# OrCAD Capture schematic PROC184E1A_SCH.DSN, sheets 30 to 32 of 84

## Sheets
30 34. GESI EXPANSION_CONN: size C; title: GESI_EXP_CONN; note: PROC184_SCH
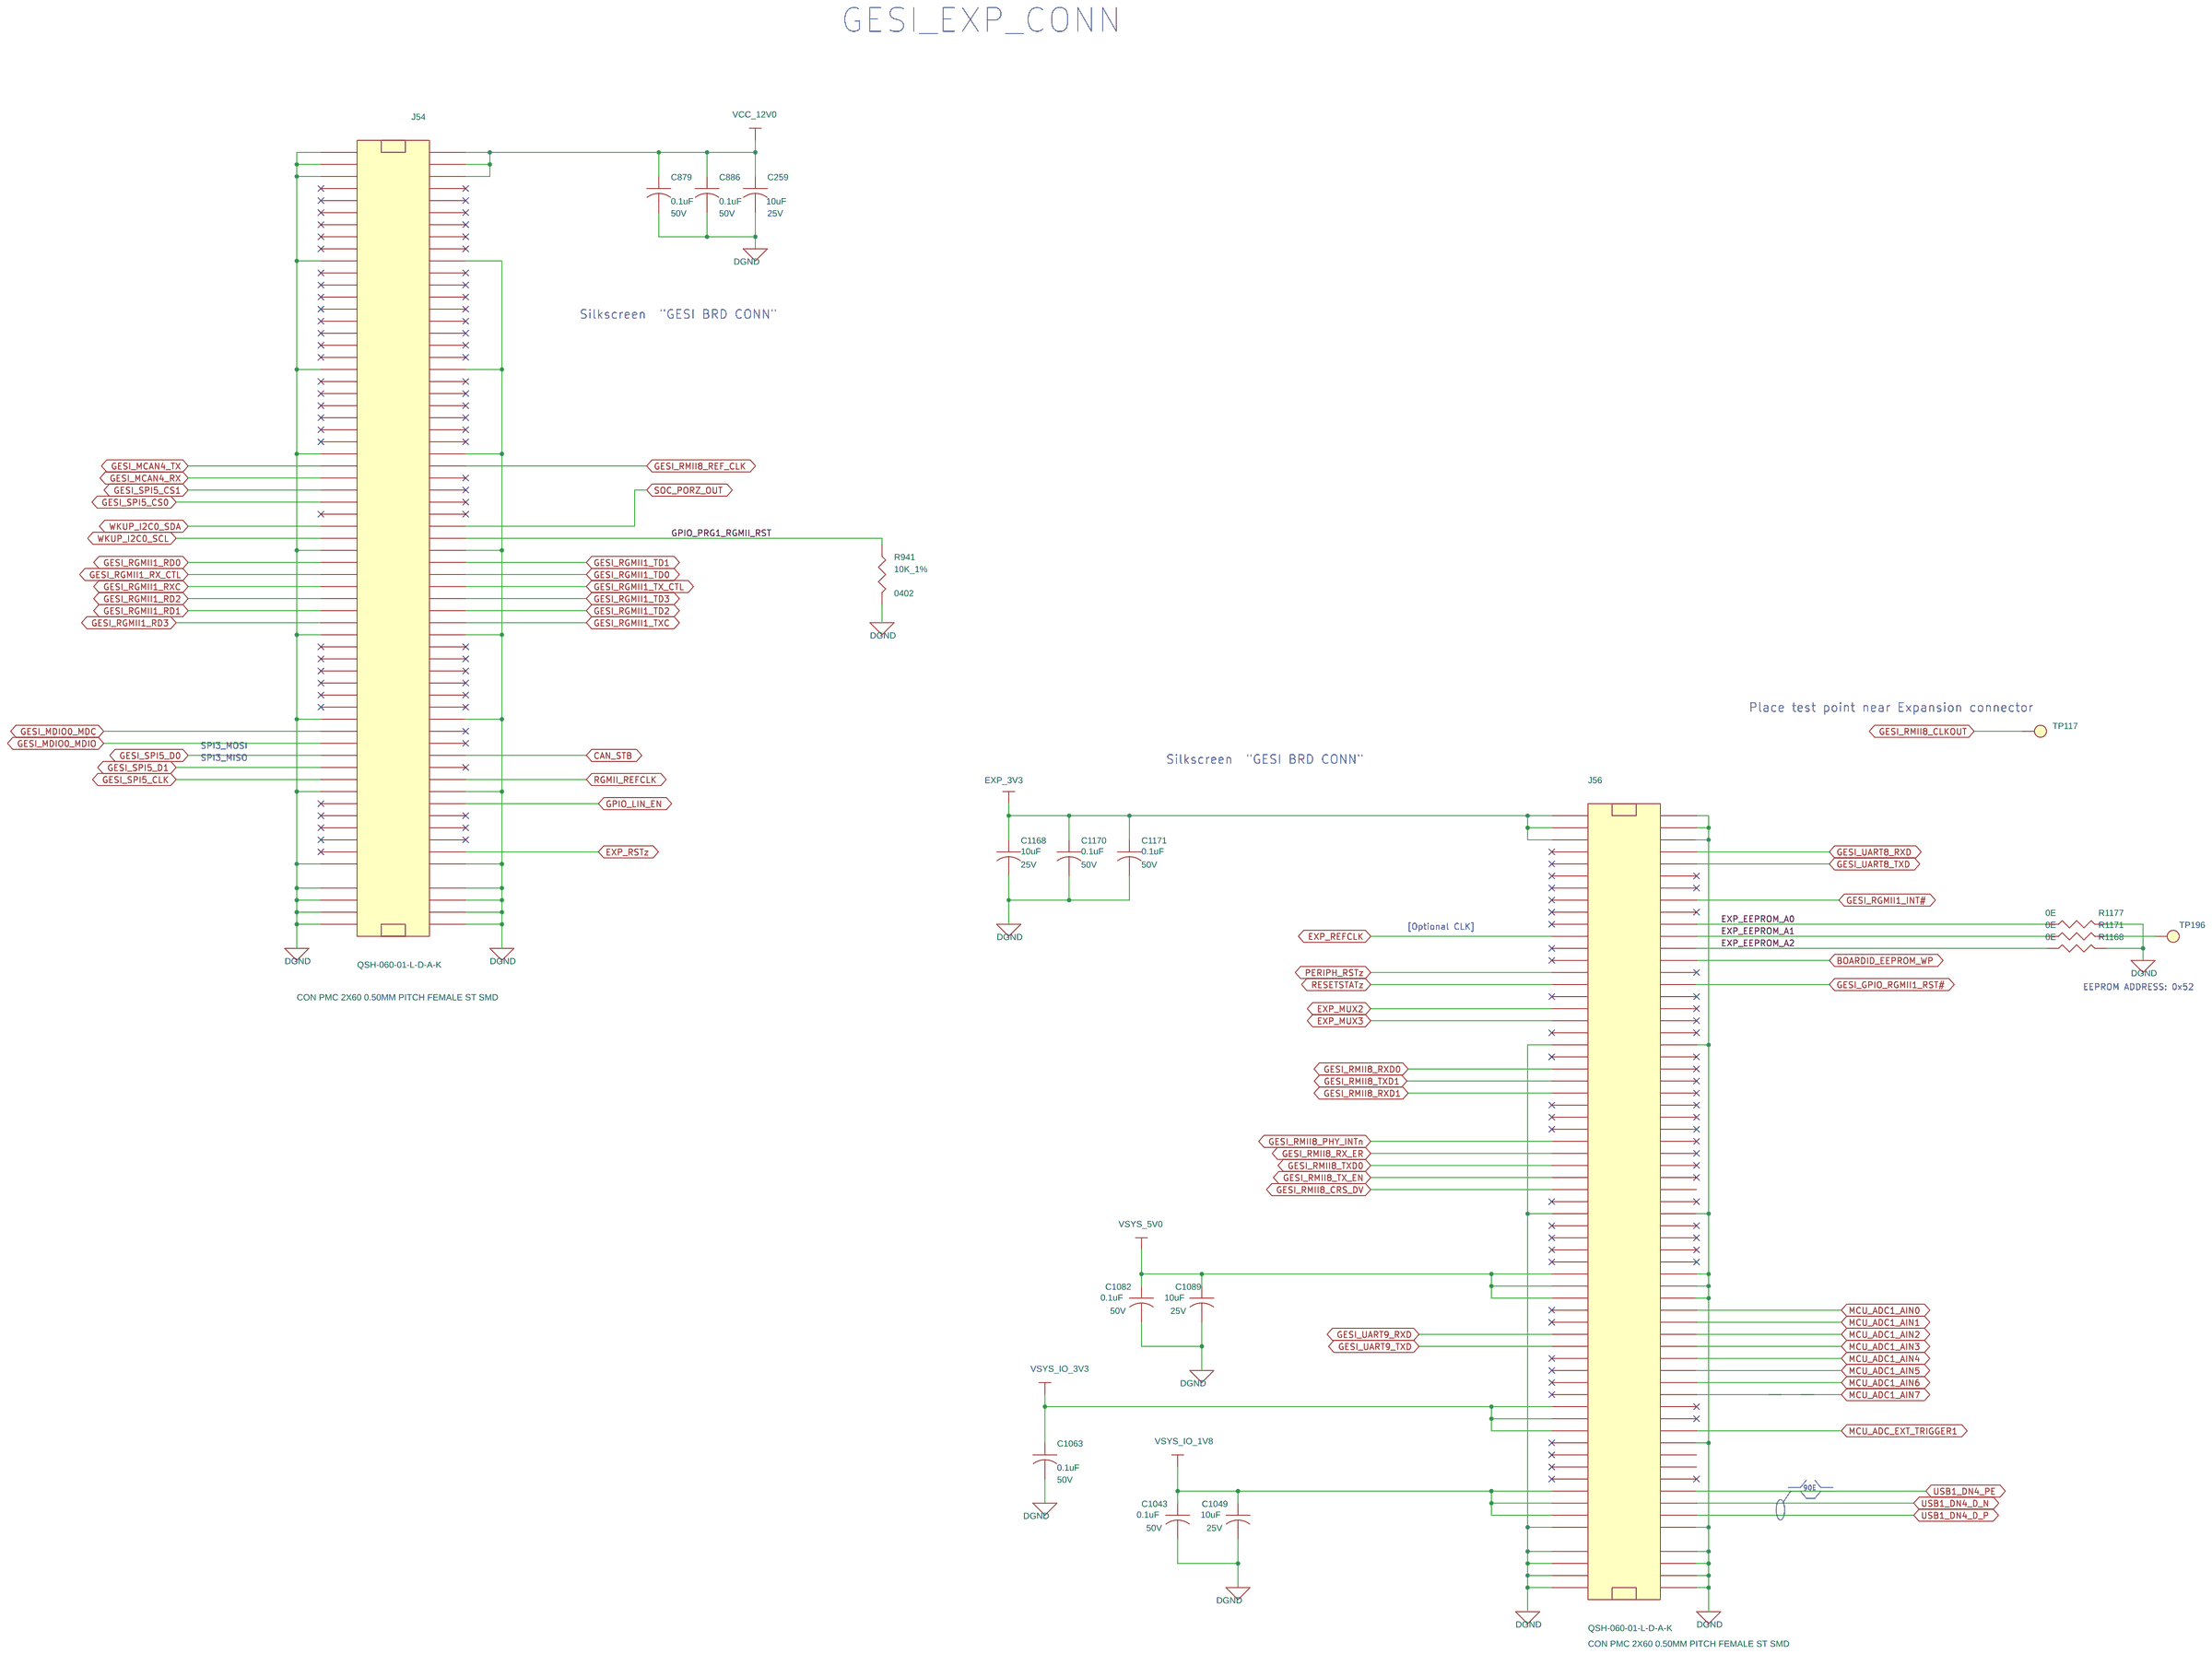
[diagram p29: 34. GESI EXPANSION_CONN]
31 35. CSI2 EXPANSION CONNECTORS: size C; title: CSI2 EXPANSION CONNECTORS; note: PROC184_SCH
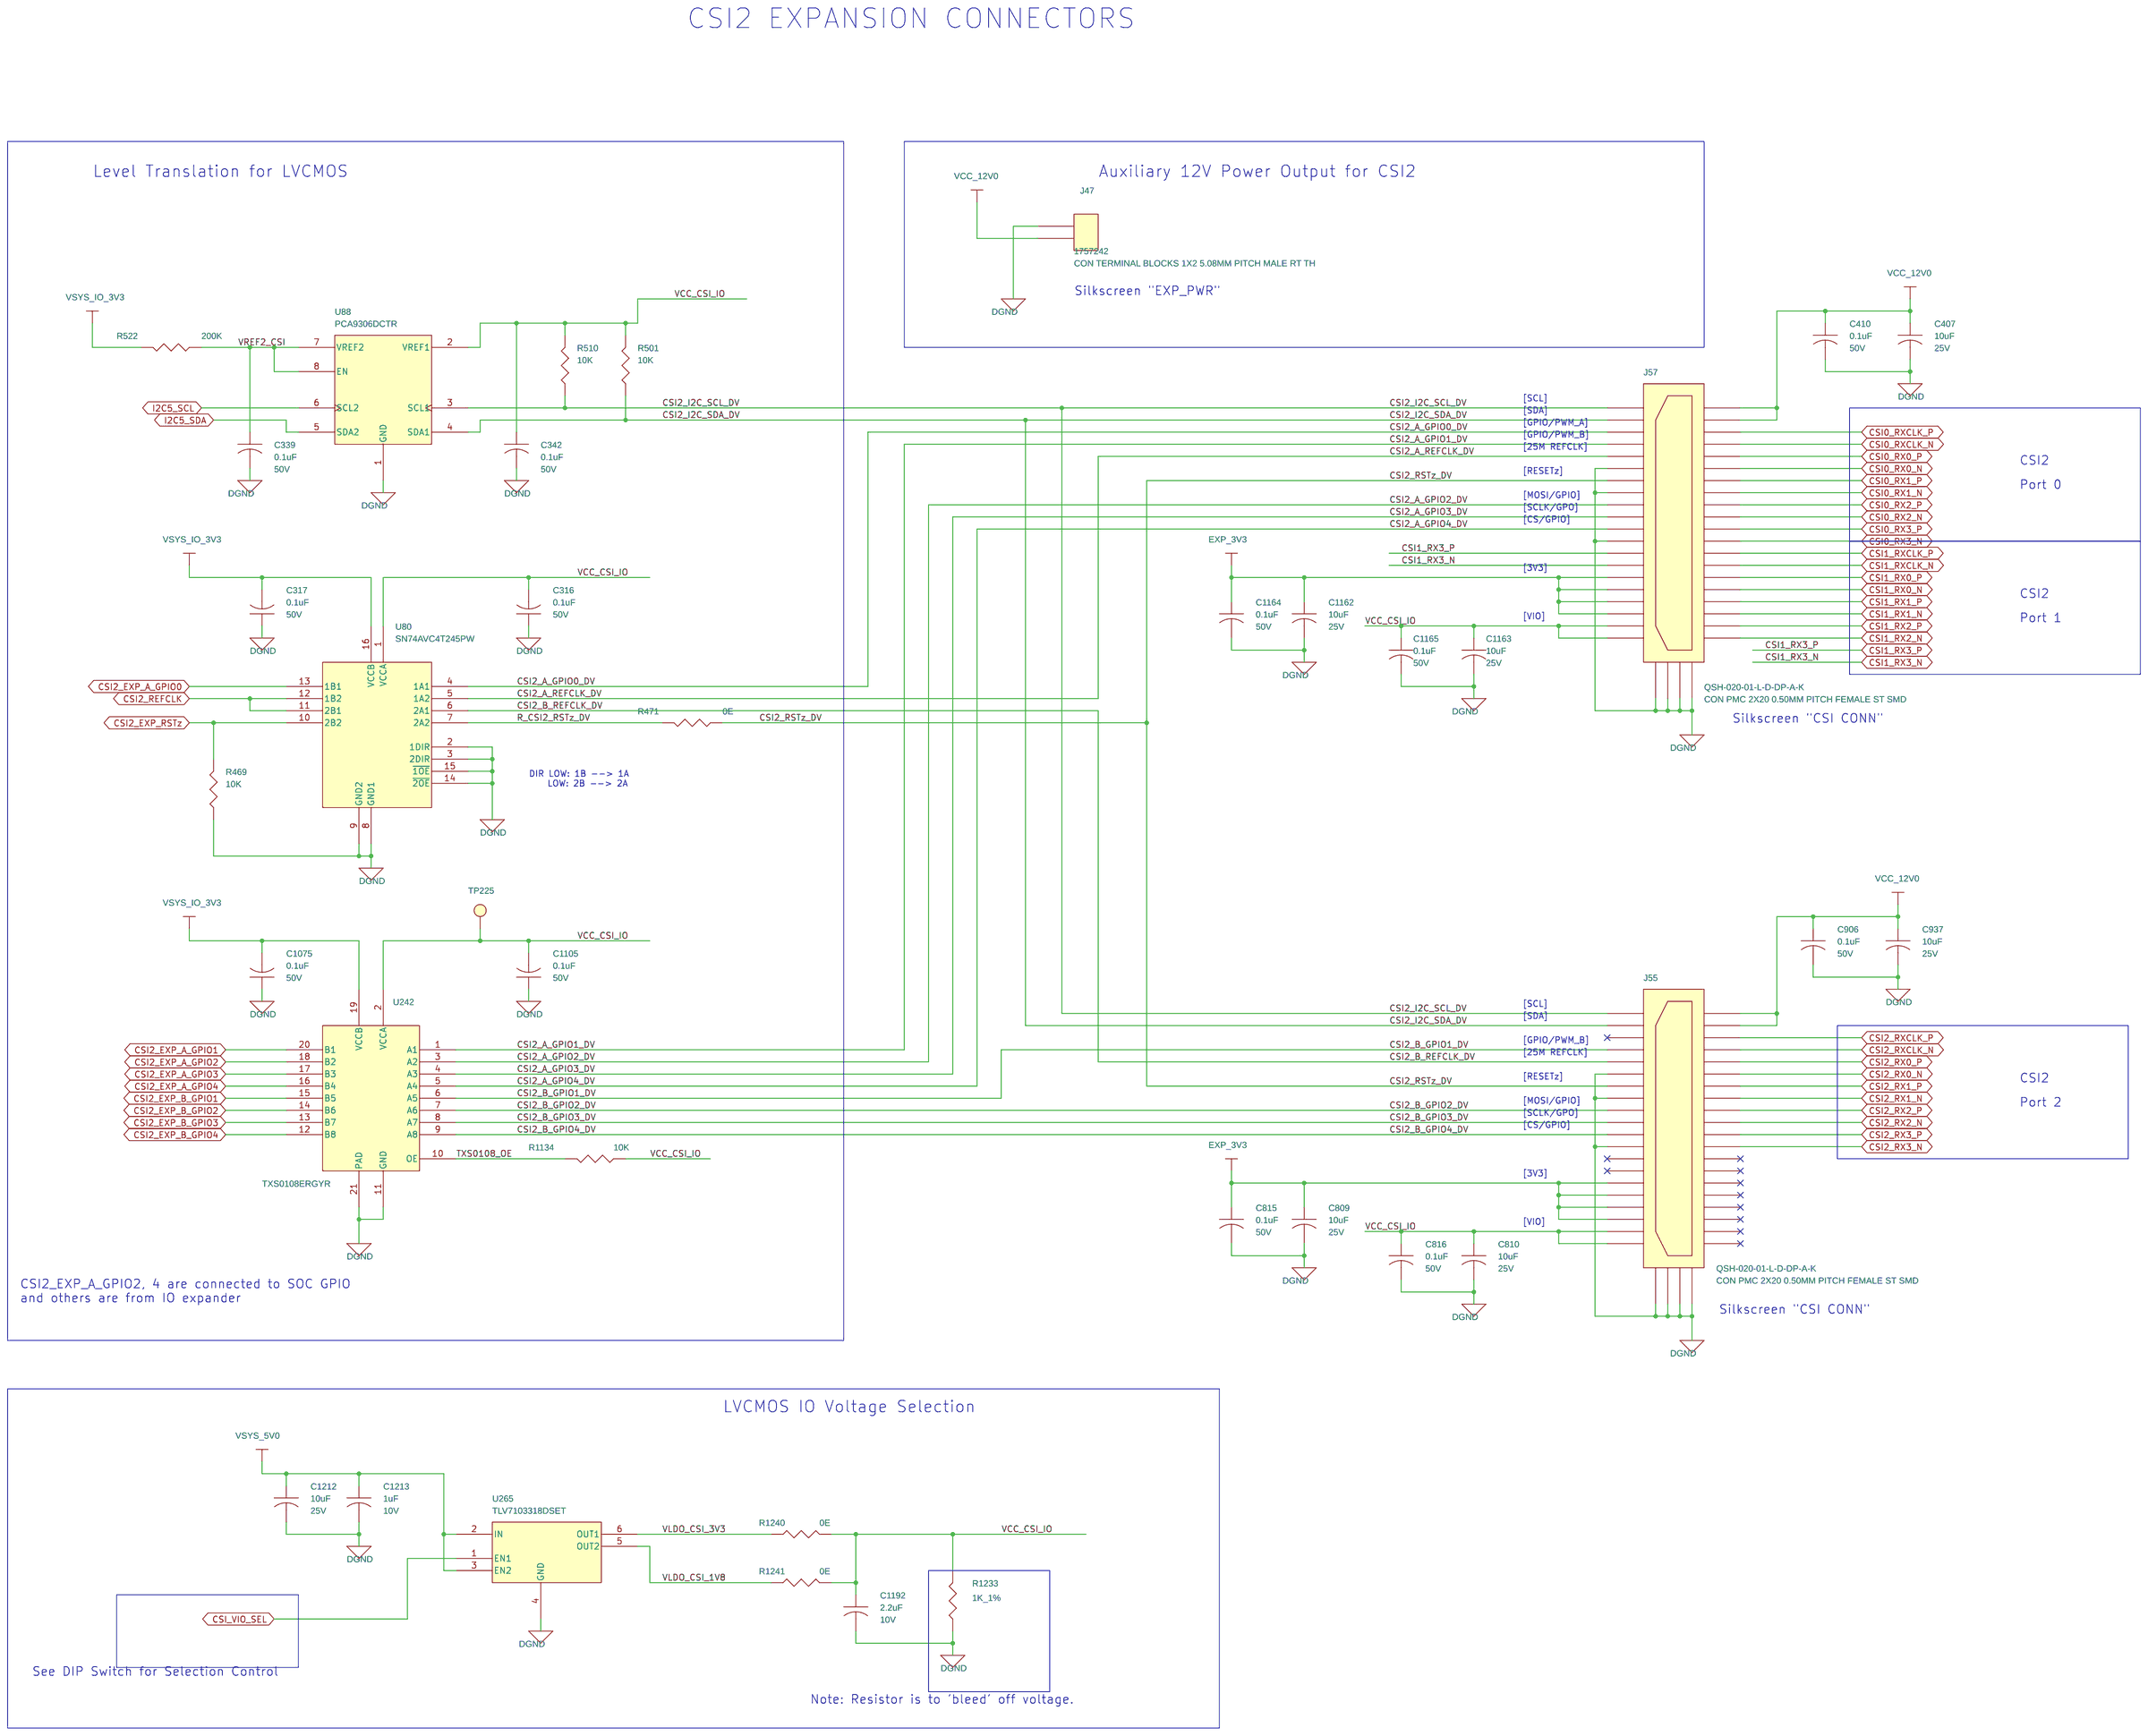
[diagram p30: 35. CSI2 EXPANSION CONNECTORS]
32 36. SERDES CLOCK GENERATOR #1: size C; title: SERDES CLOCK GENERATOR #1; note: PROC184_SCH
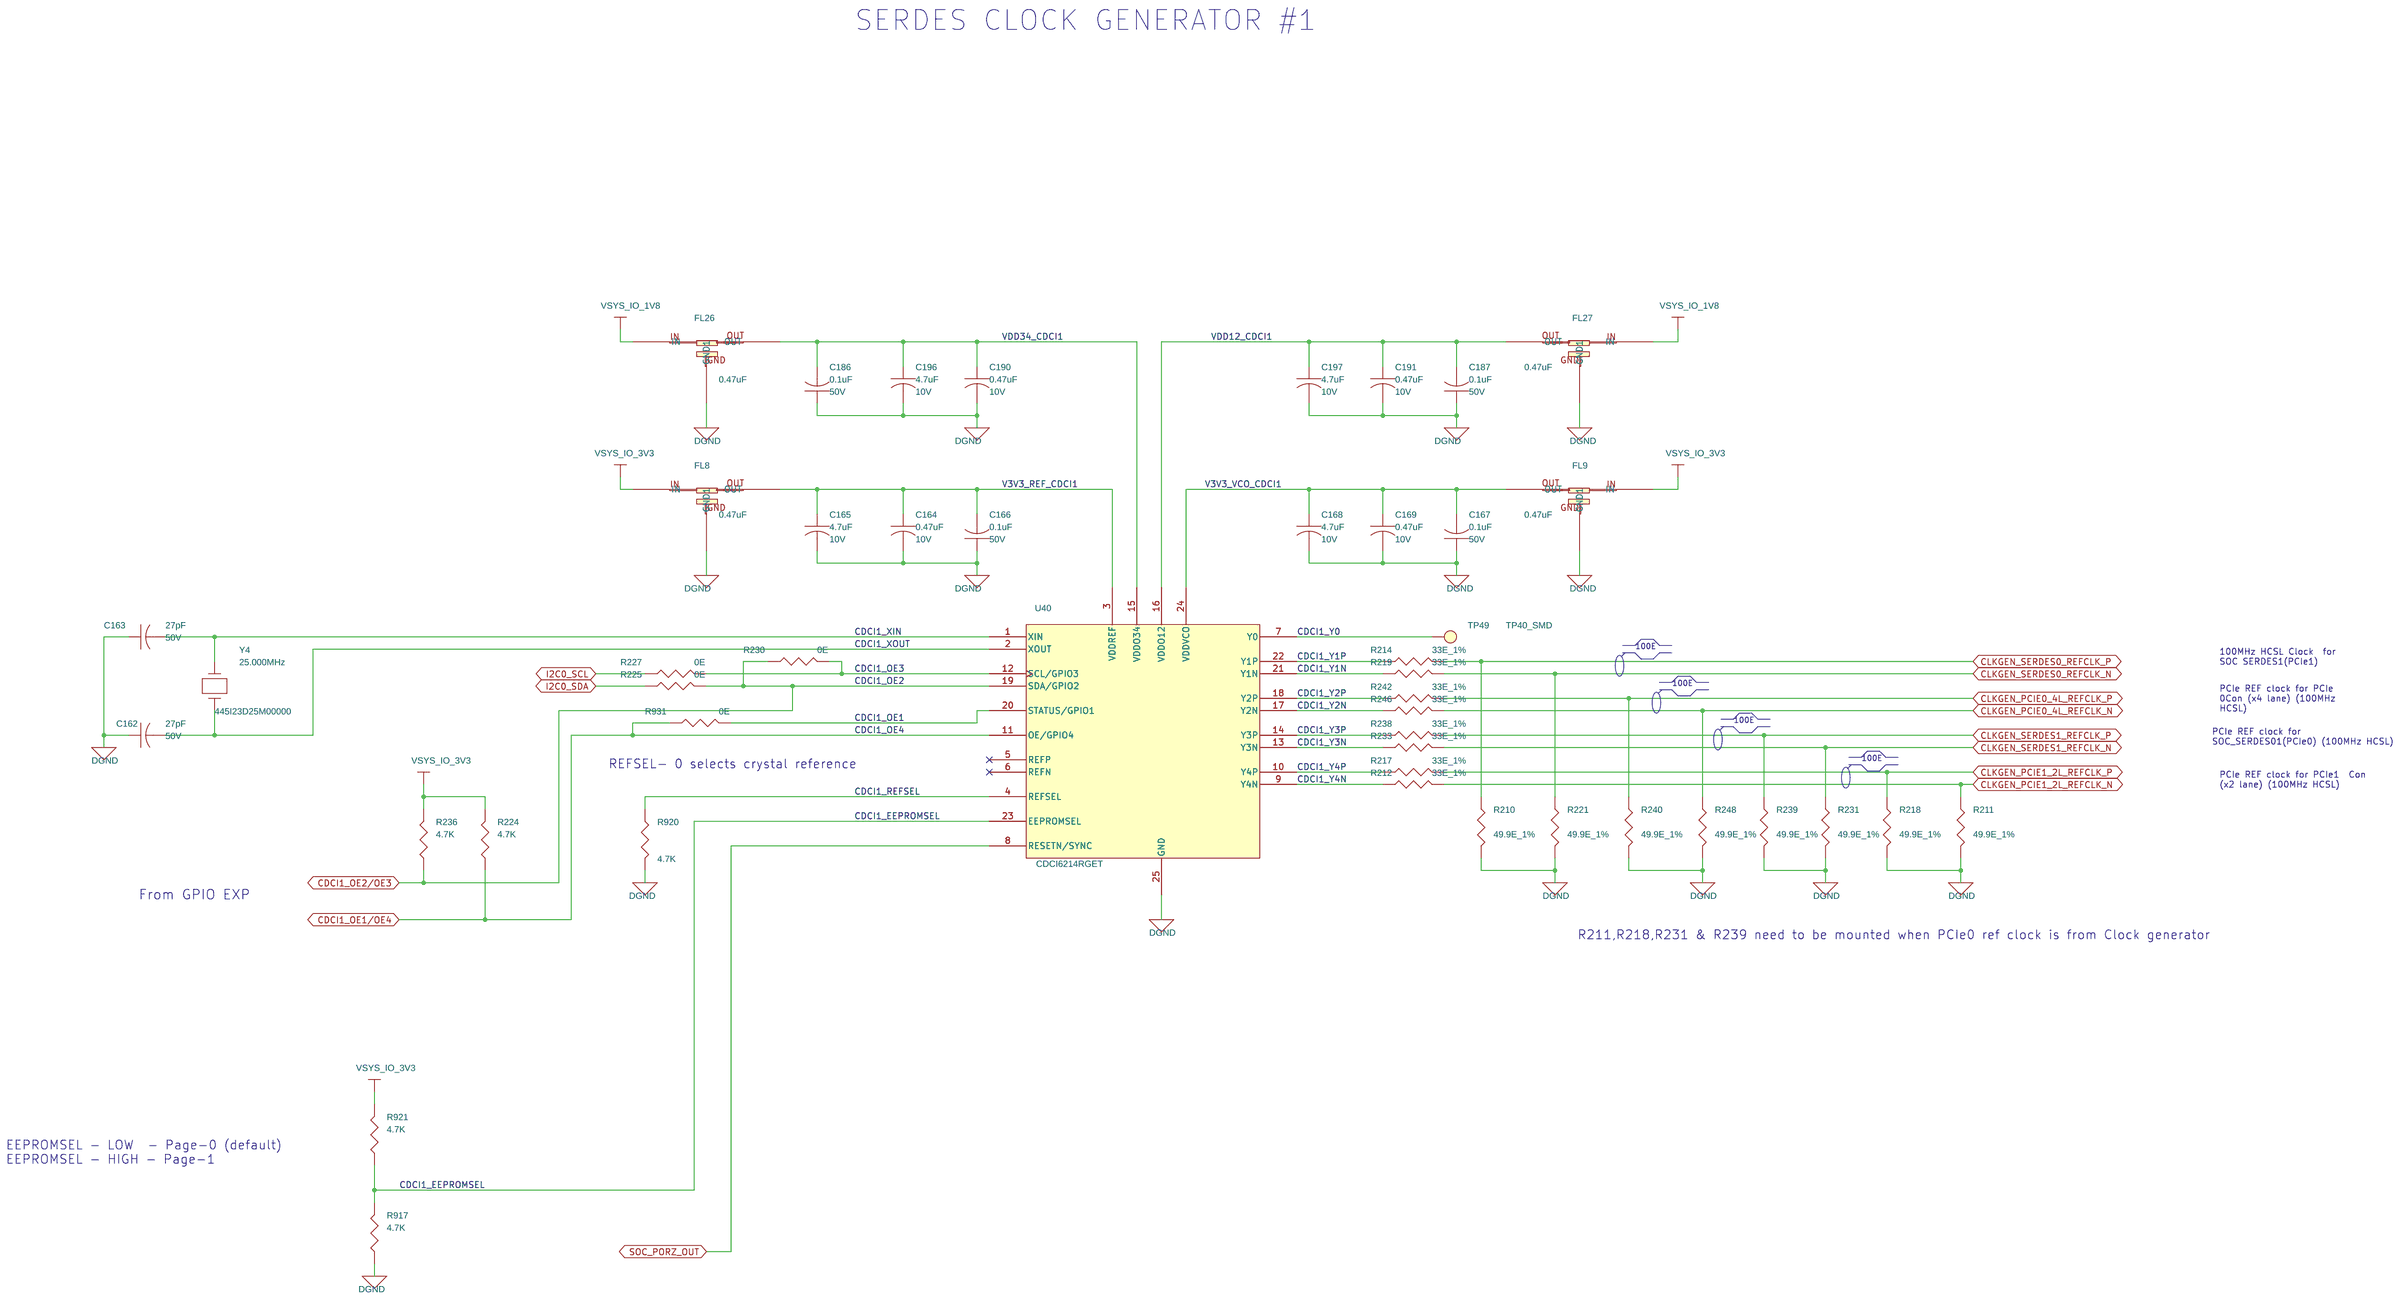
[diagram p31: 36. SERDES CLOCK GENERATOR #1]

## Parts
sheet 34. GESI EXPANSION_CONN
C259  10uF  [CAP0603_1-25]
C879  0.1uF  [CAP0402_0-75]
C886  0.1uF  [CAP0402_0-75]
C1043  0.1uF  [CAP0402_0-75]
C1049  10uF  [CAP0603_1-25]
C1063  0.1uF  [CAP0402_0-75]
C1082  0.1uF  [CAP0402_0-75]
C1089  10uF  [CAP0603_1-25]
C1168  10uF  [CAP0603_1-25]
C1170  0.1uF  [CAP0402_0-75]
C1171  0.1uF  [CAP0402_0-75]
J54  CON_PMC_2X60_F  [CON_PMC60X2_HQCD-060_S_S_S_3-3]
J56  CON_PMC_2X60_F  [CON_PMC60X2_HQCD-060_S_S_S_3-3]
R941  10K_1%  [RES0402_0-5]
R1168  0E  [RES0402_0-5]
R1171  0E  [RES0402_0-5]
R1177  0E  [RES0402_0-5]
TP117  TP30_SMD  [TP30_SMD]
TP196  TP40_SMD  [TP40_SMD]
sheet 35. CSI2 EXPANSION CONNECTORS
C316  0.1uF  [CAP0402_0-75]
C317  0.1uF  [CAP0402_0-75]
C339  0.1uF  [CAP0402_0-75]
C342  0.1uF  [CAP0402_0-75]
C407  10uF  [CAP0603_1-25]
C410  0.1uF  [CAP0402_0-75]
C809  10uF  [CAP0603_1-25]
C810  10uF  [CAP0603_1-25]
C815  0.1uF  [CAP0402_0-75]
C816  0.1uF  [CAP0402_0-75]
C906  0.1uF  [CAP0402_0-75]
C937  10uF  [CAP0603_1-25]
C1075  0.1uF  [CAP0402_0-75]
C1105  0.1uF  [CAP0402_0-75]
C1162  10uF  [CAP0603_1-25]
C1163  10uF  [CAP0603_1-25]
C1164  0.1uF  [CAP0402_0-75]
C1165  0.1uF  [CAP0402_0-75]
C1192  2.2uF  [CAP0402_0-75]
C1212  10uF  [CAP0603_1-25]
C1213  1uF  [CAP0402_0-75]
J47  CON_TRBLK_1X2  [CON_TB1X2_1757242_P_R_T_8-6]
J55  CON_PMC_2X20_F  [CON_PMC2X20_QSH-020-01-D-DP-A_S_S_S_3-4]
J57  CON_PMC_2X20_F  [CON_PMC2X20_QSH-020-01-D-DP-A_S_S_S_3-4]
R469  10K  [RES0402_0-5]
R471  0E  [RES0402_0-5]
R501  10K  [RES0402_0-5]
R510  10K  [RES0402_0-5]
R522  200K  [RES0402_0-5]
R1134  10K  [RES0402_0-5]
R1233  1K_1%  [RES0402_0-5]
R1240  0E  [RES0402_0-5]
R1241  0E  [RES0402_0-5]
TP225  TP40_SMD  [TP40_SMD]
U80  SN74AVC4T245PW  [TSSOP16_25-59_205X180]
U88  PCA9306DCTR  [SSOP8_25-59_120X110_1-3]
U242  TXS0108ERGYR  [QFN20_19-68_185X145_1]
U265  TLV7103318DSET  [WSON6_19-68_60X60]
sheet 36. SERDES CLOCK GENERATOR #1
C162  27pF  [CAP0402_0-75]
C163  27pF  [CAP0402_0-75]
C164  0.47uF  [CAP0402_0-75]
C165  4.7uF  [CAP0402_0-75]
C166  0.1uF  [CAP0402_0-75]
C167  0.1uF  [CAP0402_0-75]
C168  4.7uF  [CAP0402_0-75]
C169  0.47uF  [CAP0402_0-75]
C186  0.1uF  [CAP0402_0-75]
C187  0.1uF  [CAP0402_0-75]
C190  0.47uF  [CAP0402_0-75]
C191  0.47uF  [CAP0402_0-75]
C196  4.7uF  [CAP0402_0-75]
C197  4.7uF  [CAP0402_0-75]
FL8  0.47uF  [EMIFIL_NFM21P_0805]
FL9  0.47uF  [EMIFIL_NFM21P_0805]
FL26  0.47uF  [EMIFIL_NFM21P_0805]
FL27  0.47uF  [EMIFIL_NFM21P_0805]
R210  49.9E_1%  [RES0402_0-5]
R211  49.9E_1%  [RES0402_0-5]
R212  33E_1%  [RES0402_0-5]
R214  33E_1%  [RES0402_0-5]
R217  33E_1%  [RES0402_0-5]
R218  49.9E_1%  [RES0402_0-5]
R219  33E_1%  [RES0402_0-5]
R221  49.9E_1%  [RES0402_0-5]
R224  4.7K  [RES0402_0-5]
R225  0E  [RES0402_0-5]
R227  0E  [RES0402_0-5]
R230  0E  [RES0402_0-5]
R231  49.9E_1%  [RES0402_0-5]
R233  33E_1%  [RES0402_0-5]
R236  4.7K  [RES0402_0-5]
R238  33E_1%  [RES0402_0-5]
R239  49.9E_1%  [RES0402_0-5]
R240  49.9E_1%  [RES0402_0-5]
R242  33E_1%  [RES0402_0-5]
R246  33E_1%  [RES0402_0-5]
R248  49.9E_1%  [RES0402_0-5]
R917  4.7K  [RES0402_0-5]
R920  4.7K  [RES0402_0-5]
R921  4.7K  [RES0402_0-5]
R931  0E  [RES0402_0-5]
TP49  TP40_SMD  [TP40_SMD]
U40  CDCI6214RGET  [QFN24_19-68_160X160_1]
Y4  25.000MHz  [XTAL_ABM3_205X130_SMD_1-4]

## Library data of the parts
C259 C407 C937 = CAP: CAP CERAMIC 10uF 25V 20% X5R 0603; Automotive Alternate_mfr_name: TDK; Automotive Alternate_mfr_part_number: CGA5L1X7R1H106K160AC; Chkd/date: MANIRAJA/040718; Crtd /date: MANIRAJA/040718; Custom_Duty: 15%; Customs_HS_Code: 85322990; Direct Alternate_mfr_name: SAMSUNG; Direct Alternate_mfr_part_number: CL31A106KBHNNNE; Distributor_name: DIGIKEY; Distributor_part_number: 490-10991-1-ND; Footprint Path: Y:\MIS_DATABASE\Library\ALTIUM_TOOL\PCB_FOOTPRINTS\Altium_Footprint_Lib.PcbLib; Height: 1.20MM; Library Path: Y:\MIS_DATABASE\Library\ALTIUM_TOOL\SCHEMATICS_PARTS\MS_DISCRETE_Library.schlib; Manufacturer: TDK CORPORATION; Mfr_name: MURATA; Mfr_part_number: ZRB18AR61E106ME01L; Mistral Part No: 120018070001-R; Package: 0603; Part_type: CAPACITORS\CERAMIC; Project: CABS_VME_DIO; RoHS: RoHS; Temperature: -55°C+85°C; Tolerance: 20%; Voltage: 25V; Wattage: NA; Weight: 2mg; Datasheet: Y:\MIS_DATABASE\DATASHEETS\CAPACITORS\ZRB18AR61E106ME01L.PDF
C166 C167 C186 C187 C316 C317 C339 C342 C410 C815 C816 C879 C886 C906 C1043 C1063 C1075 C1082 C1105 C1164 C1165 C1170 C1171 = CAP: CAP CERAMIC 0.1uF 50V 10% X7R 0402; Automotive Alternate_mfr_name: TDK; Automotive Alternate_mfr_part_number: CGA2B3X7R1H104K050BB; Chkd/date: MANIRAJA/261020; Crtd /date: ALVY/211020; Custom_Duty: 15%; Customs_HS_Code: 85322990; Direct Alternate_mfr_name: TDK; Direct Alternate_mfr_part_number: C1005X7R1H104K050BE; Distributor_name: DIGIKEY; Distributor_part_number: 490-10700-1-ND; Footprint Path: Y:\MIS_DATABASE\Library\ALTIUM_TOOL\PCB_FOOTPRINTS\Altium_Footprint_Lib.PcbLib; Height: 0.55MM; Library Path: Y:\MIS_DATABASE\Library\ALTIUM_TOOL\SCHEMATICS_PARTS\MS_DISCRETE_Library.schlib; Manufacturer: MURATA; Mfr_name: MURATA; Mfr_part_number: GRM155R71H104KE14D; Mistral Part No: 120011100014-R; Package: 0402; Part_type: CAPACITORS\CERAMIC; Project: J7_CP; RoHS: RoHS; Temperature: -55°C+125°C; Tolerance: 10%; Voltage: 50V; Wattage: NA; Weight: 3.1mg; Datasheet: Y:\MIS_DATABASE\DATASHEETS\CAPACITORS\GRM155R71H104KE14.PDF
C809 C810 C1049 C1089 C1162 C1163 C1168 C1212 = CAP: CAP CERAMIC 10uF 25V 20% X5R 0603; Automotive Alternate_mfr_name: MURATA; Automotive Alternate_mfr_part_number: GRT188R61E106ME13D; Chkd/date: MANIRAJA/040718; Crtd /date: MANIRAJA/040718; Custom_Duty: 15%; Customs_HS_Code: 85322990; Direct Alternate_mfr_name: TDK; Direct Alternate_mfr_part_number: C1608X5R1E106M080AC; Distributor_name: DIGIKEY; Distributor_part_number: 490-10991-1-ND; Footprint Path: Y:\MIS_DATABASE\Library\ALTIUM_TOOL\PCB_FOOTPRINTS\Altium_Footprint_Lib.PcbLib; Height: 1.20MM; Library Path: Y:\MIS_DATABASE\Library\ALTIUM_TOOL\SCHEMATICS_PARTS\MS_DISCRETE_Library.schlib; Manufacturer: MURATA; Mfr_name: MURATA; Mfr_part_number: ZRB18AR61E106ME01L; Mistral Part No: 120018070001-R; Package: 0603; Part_type: CAPACITORS\CERAMIC; Project: CABS_VME_DIO; RoHS: RoHS; Temperature: -55°C+85°C; Tolerance: 20%; Voltage: 25V; Wattage: NA; Weight: 2mg; Datasheet: Y:\MIS_DATABASE\DATASHEETS\CAPACITORS\ZRB18AR61E106ME01L.PDF
J54 J56 = CON_PMC_60X2_HQCD: CON PMC 2X60 0.50MM PITCH FEMALE ST SMD; Chkd/date: MANIRAJA/230817; Crtd /date: MUDDU/020610; Custom_Duty: 24%; Customs_HS_Code: 85369090; Distributor_name: DIGIKEY; Distributor_part_number: SAM10652-ND; Height: 3.25MM; Manufacturer: SAMTEC; Mfr_name: SAMTEC; Mfr_part_number: QSH-060-01-L-D-A-K; Mistral Part No: 150010060004-R; Package: SMD; Part_type: CONNECTOR\PMC; Project: CENTAURUS; RoHS: RoHS; Temperature: -55°C+125°C; Tolerance: NA; Voltage: NA; Wattage: NA; Weight: NA; Datasheet: Y:\MIS_DATABASE\DATASHEETS\CONNECTORS\QSH.PDF
R941 = RESISTOR: RES 10K 1/16W 1% 0402; Chkd/date: VASANTHA/201216; Crtd /date: GEETHA/290506; Custom_Duty: 15%; Customs_HS_Code: 85332119; Distributor_name: DIGIKEY; Distributor_part_number: 311-10.0KLRTR-ND; Footprint Path: Y:\MIS_DATABASE\Library\ALTIUM_TOOL\PCB_FOOTPRINTS\Altium_Footprint_Lib.PcbLib; Height: 0.40MM; Library Path: Y:\MIS_DATABASE\Library\ALTIUM_TOOL\SCHEMATICS_PARTS\MS_DISCRETE_Library.schlib; Manufacturer: YAGEO AMERICA; Mfr_name: YAGEO AMERICA; Mfr_part_number: RC0402FR-0710KL; Mistral Part No: 110015090015-R; Package: 0402; Part_type: RESISTORS\FIXED; Project: VOCERA; RoHS: RoHS; Temperature: -55°C+155°C; Tolerance: 1%; Voltage: NA; Wattage: 1/16W; Weight: 0.65mg; Datasheet: Y:\MIS_DATABASE\DATASHEETS\RESISTORS\RCXXXXL-SER_MAR18.PDF
R230 R931 R1168 R1177 R1240 R1241 = RESISTOR: RES 0E 1/10W JUMPER 0402; Chkd/date: VASANTHA/061216; Crtd /date: NAVEED/201014; Custom_Duty: 15%; Customs_HS_Code: 85332119; Distributor_name: DIGIKEY; Distributor_part_number: P0.0JCT-ND; Footprint Path: Y:\MIS_DATABASE\Library\ALTIUM_TOOL\PCB_FOOTPRINTS\Altium_Footprint_Lib.PcbLib; Height: 0.40MM; IBISSP_MODLES: VALUE REPEATING 2 TIME; Library Path: Y:\MIS_DATABASE\Library\ALTIUM_TOOL\SCHEMATICS_PARTS\MS_DISCRETE_Library.schlib; Manufacturer: PANASONIC-ECG; Mfr_name: PANASONIC-ECG; Mfr_part_number: ERJ-2GE0R00X; Mistral Part No: 110018030052-R; Package: 0402; Part_type: RESISTORS\FIXED; Project: AEGIS POM; RoHS: RoHS; Temperature: -55°C+155°C; Tolerance: NA; Voltage: NA; Wattage: 1/10W; Weight: 0.8mg; Datasheet: Y:\MIS_DATABASE\DATASHEETS\RESISTORS\PAN-ERJSER_NOV17.PDF
R225 R227 R471 R1171 = RESISTOR: RES 0E 1/10W JUMPER 0402; Assembly_Instruction: DNI; Chkd/date: VASANTHA/061216; Crtd /date: NAVEED/201014; Custom_Duty: 15%; Customs_HS_Code: 85332119; Distributor_name: DIGIKEY; Distributor_part_number: P0.0JCT-ND; Footprint Path: Y:\MIS_DATABASE\Library\ALTIUM_TOOL\PCB_FOOTPRINTS\Altium_Footprint_Lib.PcbLib; Height: 0.40MM; IBISSP_MODLES: VALUE REPEATING 2 TIME; Library Path: Y:\MIS_DATABASE\Library\ALTIUM_TOOL\SCHEMATICS_PARTS\MS_DISCRETE_Library.schlib; Manufacturer: PANASONIC-ECG; Mfr_name: PANASONIC-ECG; Mfr_part_number: ERJ-2GE0R00X; Mistral Part No: 110018030052-R; Package: 0402; Part_type: RESISTORS\FIXED; Project: AEGIS POM; RoHS: RoHS; Temperature: -55°C+155°C; Tolerance: NA; Voltage: NA; Wattage: 1/10W; Weight: 0.8mg; Datasheet: Y:\MIS_DATABASE\DATASHEETS\RESISTORS\PAN-ERJSER_NOV17.PDF
TP117 = TESTPOINT: TESTPOINT CIR 30 SMD; Chkd/date: SHREESHAIL/171006; Crtd /date: MAZHAR/171006; Custom_Duty: NA; Customs_HS_Code: NA; Distributor_name: NA; Distributor_part_number: NA; Footprint Path: Y:\MIS_DATABASE\Library\ALTIUM_TOOL\PCB_FOOTPRINTS\Altium_Footprint_Lib.PcbLib; Height: NA; Library Path: Y:\MIS_DATABASE\Library\ALTIUM_TOOL\SCHEMATICS_PARTS\MS_DISCRETE_Library.schlib; MECHANICAL 3D STEP FILE: NA; Manufacturer: LOCAL; Mfr_name: LOCAL; Mistral Part No: 130009030930; Package: SMD; Project: BT MODULE_CSRBC04; RoHS: NA; Temperature: NA; Tolerance: NA; Voltage: NA; Wattage: NA; Weight: NA; Datasheet: NA
TP49 TP196 TP225 = TESTPOINT: TESTPOINT CIR 40 SMD; Chkd/date: MAZHAR/190505; Crtd /date: MAZHAR/190505; Distributor_name: NA; Distributor_part_number: NA; Footprint Path: Y:\MIS_DATABASE\Library\ALTIUM_TOOL\PCB_FOOTPRINTS\Altium_Footprint_Lib.PcbLib; Height: NA; Library Path: Y:\MIS_DATABASE\Library\ALTIUM_TOOL\SCHEMATICS_PARTS\MS_DISCRETE_Library.schlib; MECHANICAL 3D STEP FILE: NA; Manufacturer: LOCAL; Mfr_name: LOCAL; Mistral Part No: 130009030933; Package: SMD; Project: RAINIER-3; RoHS: NA; Temperature: NA; Tolerance: NA; Voltage: NA; Wattage: NA; Weight: NA; Datasheet: NA
C1192 = CAP: CAP CERAMIC 2.2uF 10V 10% X5R 0402; Automotive Alternate_mfr_name: MURATA; Automotive Alternate_mfr_part_number: GRT155R61E225KE13D; Chkd/date: MANIRAJA/251120; Crtd /date: ALVY/241120; Custom_Duty: 15%; Customs_HS_Code: 85322990; Direct Alternate_mfr_name: TDK; Direct Alternate_mfr_part_number: C1005X5R1E225K050BC; Distributor_name: MOUSER; Distributor_part_number: 81-GRM155R61A225K01D; Footprint Path: Y:\MIS_DATABASE\Library\ALTIUM_TOOL\PCB_FOOTPRINTS\Altium_Footprint_Lib.PcbLib; Height: 0.55MM; Library Path: Y:\MIS_DATABASE\Library\ALTIUM_TOOL\SCHEMATICS_PARTS\MS_DISCRETE_Library.schlib; Manufacturer: MURATA; Mfr_name: MURATA; Mfr_part_number: GRM155R61A225KE01D; Mistral Part No: 120011100038-R; Package: 0402; Part_type: CAPACITORS\CERAMIC; Project: PLCC_DIGITAL BRD PROTO; RoHS: RoHS; Temperature: -55°C+85°C; Tolerance: 10%; Voltage: 10V; Wattage: NA; Weight: 1.6mg; Datasheet: Y:\MIS_DATABASE\DATASHEETS\CAPACITORS\MURATA-GXX-SER_NOV17.PDF
C1213 = CAP: CAP CERAMIC 1uF 10V 10% X7S AUTO 0402; Automotive Alternate_mfr_name: TAIYO YUDEN; Automotive Alternate_mfr_part_number: EMK105BJ105KVHF; Chkd/date: MANIRAJA/100918; Crtd /date: ALVY/100918; Custom_Duty: 15%; Customs_HS_Code: 85322990; Direct Alternate_mfr_name: YAGEO AMERICA; Direct Alternate_mfr_part_number: CC0402KRX5R7BB105; Distributor_name: DIGIKEY; Distributor_part_number: 490-13409-1-ND; Footprint Path: Y:\MIS_DATABASE\Library\ALTIUM_TOOL\PCB_FOOTPRINTS\Altium_Footprint_Lib.PcbLib; Height: 0.70MM; Library Path: Y:\MIS_DATABASE\Library\ALTIUM_TOOL\SCHEMATICS_PARTS\MS_DISCRETE_Library.schlib; Manufacturer: TDK CORPORATION; Mfr_name: MURATA; Mfr_part_number: GCM155C71A105KE38D; Mistral Part No: 120018090021-R; Package: 0402; Part_type: CAPACITORS\CERAMIC; Project: SMART-M_SCRIPTALK_PB; RoHS: RoHS; Temperature: -55°C+125°C; Tolerance: 10%; Voltage: 10V; Wattage: NA; Weight: 6mg; Datasheet: Y:\MIS_DATABASE\DATASHEETS\CAPACITORS\MURATA-GCM-SER.PDF
J47 = CON_TRBLK_2X1: CON TERMINAL BLOCKS 1X2 5.08MM PITCH MALE RT TH; Chkd/date: MANIRAJA/260218; Crtd /date: ALVY/260218; Custom_Duty: 24%; Customs_HS_Code: 85369090; Distributor_name: DIGIKEY; Distributor_part_number: 277-1106-ND; Footprint Path: Y:\MIS_DATABASE\Library\ALTIUM_TOOL\PCB_FOOTPRINTS\Altium_Footprint_Lib.PcbLib; Height: 8.60MM; Library Path: Y:\MIS_DATABASE\Library\ALTIUM_TOOL\SCHEMATICS_PARTS\MS_CONNECTOR_Library.schlib; Manufacturer: PH0ENIX; Mfr_name: PH0ENIX; Mfr_part_number: 1757242; Mistral Part No: 150018020024-R; Package: THRU-HOLE; Part_type: CONNECTOR\TERMINAL BLOCK; Project: GRACO SMART MODULE; RoHS: RoHS; Temperature: NA; Tolerance: NA; Voltage: NA; Wattage: NA; Weight: 0.96g; Datasheet: Y:\MIS_DATABASE\DATASHEETS\CONNECTORS\1757242.PDF
J55 J57 = CON_PMC_20X2_F_DP_TI: CON PMC 2X20 0.50MM PITCH FEMALE ST SMD; Chkd/date: MANIRAJA/251018; Crtd /date: ALVY/251018; Custom_Duty: 24%; Customs_HS_Code: 85369090; Distributor_name: DIGIKEY; Distributor_part_number: SAM10648-ND; Footprint Path: Y:\MIS_DATABASE\Library\ALTIUM_TOOL\PCB_FOOTPRINTS\Altium_Footprint_Lib.PcbLib; Height: 3.33MM; Library Path: Y:\MIS_DATABASE\Library\ALTIUM_TOOL\SCHEMATICS_PARTS\MS_CONNECTOR_Library.schlib; Library Ref: CON_PMC_20X2_F_DP; Manufacturer: SAMTEC; Mfr_name: SAMTEC; Mfr_part_number: QSH-020-01-L-D-DP-A-K; Mistral Part No: 150018100049-R; Package: SMD; Part_type: CONNECTOR\PMC; Project: TI_J7ES_EVM_CP; RoHS: RoHS; Temperature: -55°C+125°C; Tolerance: NA; Voltage: NA; Wattage: NA; Weight: NA; Datasheet: Y:\MIS_DATABASE\DATASHEETS\CONNECTORS\QSH-SERIES.PDF
R469 R501 R510 R1134 = RESISTOR: RES 10K 1/16W 5% 0402; Chkd/date: VASANTHA/061216; Crtd /date: MAZHAR/230805; Custom_Duty: 15%; Customs_HS_Code: 85332119; Distributor_name: DIGIKEY; Distributor_part_number: 311-10KJRCT-ND; Footprint Path: Y:\MIS_DATABASE\Library\ALTIUM_TOOL\PCB_FOOTPRINTS\Altium_Footprint_Lib.PcbLib; Height: 0.40MM; Library Path: Y:\MIS_DATABASE\Library\ALTIUM_TOOL\SCHEMATICS_PARTS\MS_DISCRETE_Library.schlib; Manufacturer: YAGEO AMERICA; Mfr_name: YAGEO AMERICA; Mfr_part_number: RC0402JR-0710KL; Mistral Part No: 110011060021-R; Package: 0402; Part_type: RESISTORS\FIXED; Project: HSE; RoHS: RoHS; Temperature: -55°C+155°C; Tolerance: 5%; Voltage: NA; Wattage: 1/16W; Weight: 0.65mg; Datasheet: Y:\MIS_DATABASE\DATASHEETS\RESISTORS\RCXXXXL-SER_MAR18.PDF
R522 = RESISTOR: RES 200K 1/10W 5% 0402; Chkd/date: MANOJ/230414; Crtd /date: USMAN/151013; Custom_Duty: 15%; Customs_HS_Code: 85332119; Distributor_name: DIGIKEY; Distributor_part_number: P200KJCT-ND; Footprint Path: Y:\MIS_DATABASE\Library\ALTIUM_TOOL\PCB_FOOTPRINTS\Altium_Footprint_Lib.PcbLib; Height: 0.40MM; Library Path: Y:\MIS_DATABASE\Library\ALTIUM_TOOL\SCHEMATICS_PARTS\MS_DISCRETE_Library.schlib; Manufacturer: PANASONIC-ECG; Mfr_name: PANASONIC-ECG; Mfr_part_number: ERJ-2GEJ204X; Mistral Part No: 110013100006-R; Package: 0402; Part_type: RESISTORS\FIXED; Project: C-BAND_SYNTH; RoHS: RoHS; Temperature: -55°C+155°C; Tolerance: 5%; Voltage: NA; Wattage: 1/10W; Weight: 0.8mg; Datasheet: Y:\MIS_DATABASE\DATASHEETS\RESISTORS\PAN-ERJSER_NOV17.PDF
R1233 = RESISTOR: RES 1K 1/10W 1% 0402; Chkd/date: VASANTHA/281216; Crtd /date: MAZHAR/150506; Custom_Duty: 15%; Customs_HS_Code: 85332119; Distributor_name: DIGIKEY; Distributor_part_number: P1.00KLCT-ND; Footprint Path: Y:\MIS_DATABASE\Library\ALTIUM_TOOL\PCB_FOOTPRINTS\Altium_Footprint_Lib.PcbLib; Height: 0.40MM; Library Path: Y:\MIS_DATABASE\Library\ALTIUM_TOOL\SCHEMATICS_PARTS\MS_DISCRETE_Library.schlib; Manufacturer: PANASONIC-ECG; Mfr_name: PANASONIC-ECG; Mfr_part_number: ERJ-2RKF1001X; Mistral Part No: 110009030411-R; Package: 0402; Part_type: RESISTORS\FIXED; Project: VOCERA; RoHS: RoHS; Temperature: -55°C+155°C; Tolerance: 1%; Voltage: NA; Wattage: 1/10W; Weight: 0.8mg; Datasheet: Y:\MIS_DATABASE\DATASHEETS\RESISTORS\PAN-ERJSER_NOV17.PDF
U80 = SN74AVC4T245PW_TSSOP16: IC 4-BIT DUAL SUPPLY BUS TRANSCEIVER TSSOP16; Chkd/date: SHREESHAIL/030506; Crtd /date: MAZHAR/270406; Custom_Duty: 15%; Customs_HS_Code: 85423100; Distributor_name: MOUSER; Distributor_part_number: 595-SN74AVC4T245PW; Height: 1.20MM; Manufacturer: TEXAS INSTRUMENTS; Mfr_name: TEXAS INSTRUMENTS; Mistral Part No: 141009030111-R; Package: TSSOP16; Part_type: ICS\DIGITAL\COMBINATIONAL; Project: VOCERA; RoHS: Sb/ Br FREE; Datasheet: Y:\MIS_DATABASE\DATASHEETS\ICS\DIGITAL\BUSTRANSCEIVER\SN74AVC4T245.PDF
U88 = PCA9306DCT_SSOP8: IC DUAL BI-DIR I2C BUS AND SMBUS VOLTAGE LEVEL TRANSLATOR SM8; Chkd/date: MAZHAR/231210; Crtd /date: BAVISH/221210; Custom_Duty: 15%; Customs_HS_Code: 85423100; Distributor_name: DIGIKEY; Distributor_part_number: 296-18509-1-ND; Footprint Path: Y:\MIS_DATABASE\Library\ALTIUM_TOOL\PCB_FOOTPRINTS\Altium_Footprint_Lib.PcbLib; Height: 1.30MM; Library Path: Y:\MIS_DATABASE\Library\ALTIUM_TOOL\SCHEMATICS_PARTS\MS_MISCINTERFACE_Library.schlib; Manufacturer: TEXAS INSTRUMENTS; Mfr_name: TEXAS INSTRUMENTS; Mistral Part No: 141010120015-R; Package: SM8; Part_type: ICS\INTERFACE\LEVEL TRANSLATOR; Project: CENTAURUS; RoHS: RoHS; Temperature: -40°C+85°C; Tolerance: NA; Voltage: NA; Wattage: NA; Weight: 59mg; Datasheet: Y:\MIS_DATABASE\DATASHEETS\ICS\INTERFACE\PCA9306XXX.PDF
U242 = TXS0108ERGYR_QFN20: IC TRANSLATOR BIDIRECTIONAL VOLTAGE-LEVEL 8BIT QFN20; Chkd/date: VASANTHA/060117; Crtd /date: BAVISH/280411; Custom_Duty: 15%; Customs_HS_Code: 85423100; Distributor_name: DIGIKEY; Distributor_part_number: 296-24806-1-ND; Height: 1.00MM; Manufacturer: TEXAS INSTRUMENTS; Mfr_name: TEXAS INSTRUMENTS; Mistral Part No: 141011040019-R; Package: QFN20; Part_type: ICS\INTERFACE; Project: OMAPL1_PEC20; RoHS: RoHS; Temperature: -40°C+85°C; Tolerance: NA; Voltage: NA; Wattage: NA; Weight: 43mg; Datasheet: Y:\MIS_DATABASE\DATASHEETS\ICS\INTERFACE\TXS0108E.PDF
U265 = TLV7103318D_WSON6: IC REGULATOR LDO LINEAR 200mA WSON6; Automotive Alternate_mfr_name: TEXAS INSTRUMENTS; Automotive Alternate_mfr_part_number: TLV7103318QDSERQ1; Chkd/date: NAVEED/080415; Crtd /date: JEBRAN/300315; Custom_Duty: 15%; Customs_HS_Code: 85423100; Distributor_name: DIGIKEY; Distributor_part_number: 296-29058-1-ND; Height: 0.80MM; Manufacturer: TEXAS INSTRUMENTS; Mfr_name: TEXAS INSTRUMENTS; Mistral Part No: 142015030017-R; Package: WSON6; Part_type: ICS\POWER\VOLTAGE REGULATOR; Project: DUET BOARDS; RoHS: RoHS; Temperature: -40°C+125°C; Tolerance: NA; Voltage: NA; Wattage: NA; Weight: NA; Datasheet: Y:\MIS_DATABASE\DATASHEETS\MISC\REGULATORS\TLV71-SER.PDF
C162 C163 = CAP: CAP CERAMIC 27pF 50V 5% C0G(NP0) 0402; Assembly_Instruction: DNI; Automotive Alternate_mfr_name: TDK; Automotive Alternate_mfr_part_number: CGA2B2C0G1H270J050BA; Chkd/date: MAZHAR/241208; Crtd /date: GEETHA/090606; Custom_Duty: 15%; Customs_HS_Code: 85322990; Direct Alternate_mfr_name: SAMSUNG; Direct Alternate_mfr_part_number: CL05C270JB5NNNC; Distributor_name: DIGIKEY; Distributor_part_number: 311-1019-1-ND; Footprint Path: Y:\MIS_DATABASE\Library\ALTIUM_TOOL\PCB_FOOTPRINTS\Altium_Footprint_Lib.PcbLib; Height: 0.55MM; Library Path: Y:\MIS_DATABASE\Library\ALTIUM_TOOL\SCHEMATICS_PARTS\MS_DISCRETE_Library.schlib; Manufacturer: YAGEO AMERICA; Mfr_name: YAGEO AMERICA; Mfr_part_number: CC0402JRNPO9BN270; Mistral Part No: 120014100024-R; Package: 0402; Part_type: CAPACITORS\CERAMIC; Project: PNAV; RoHS: RoHS; Temperature: -55°C+125°C; Tolerance: 5%; Voltage: 50V; Wattage: NA; Weight: 0.65mg; Datasheet: Y:\MIS_DATABASE\DATASHEETS\CAPACITORS\YACC-NPO.PDF
C164 C169 C190 C191 = CAP: CAP CERAMIC 0.47uF 10V 10% X7S AUTO 0402; Automotive Alternate_mfr_name: MURATA; Automotive Alternate_mfr_part_number: GCM155C71A474KE36D; Chkd/date: MANIRAJA/280918; Crtd /date: ALVY/280918; Custom_Duty: 15%; Customs_HS_Code: 85322990; Direct Alternate_mfr_name: MURATA; Direct Alternate_mfr_part_number: GCM155C71A474KE36D; Distributor_name: DIGIKEY; Distributor_part_number: 490-14427-1-ND; Footprint Path: Y:\MIS_DATABASE\Library\ALTIUM_TOOL\PCB_FOOTPRINTS\Altium_Footprint_Lib.PcbLib; Height: 0.60MM; Library Path: Y:\MIS_DATABASE\Library\ALTIUM_TOOL\SCHEMATICS_PARTS\MS_DISCRETE_Library.schlib; Manufacturer: MURATA; Mfr_name: MURATA; Mfr_part_number: GCM155C71A474KE36D; Mistral Part No: 120018090057-R; Package: 0402; Part_type: CAPACITORS\CERAMIC; Project: TI_J7_SVB-DUT; RoHS: RoHS; Temperature: -55°C+125°C; Tolerance: 10%; Voltage: 10V; Wattage: NA; Weight: 6mg; Datasheet: Y:\MIS_DATABASE\DATASHEETS\CAPACITORS\GCM155C71A474KE36D.PDF
C165 C168 C196 C197 = CAP: CAP CERAMIC 4.7uF 10V 20% X5R 0402; Automotive Alternate_mfr_name: MURATA; Automotive Alternate_mfr_part_number: GRT155R61A475ME13D; Chkd/date: VASANTHA/061216; Crtd /date: CHAITHANYA/070612; Custom_Duty: 15%; Customs_HS_Code: 85322990; Direct Alternate_mfr_name: MURATA; Direct Alternate_mfr_part_number: GRM155R61A475MEAAD; Distributor_name: DIGIKEY; Distributor_part_number: 445-8023-1-ND; Footprint Path: Y:\MIS_DATABASE\Library\ALTIUM_TOOL\PCB_FOOTPRINTS\Altium_Footprint_Lib.PcbLib; Height: 0.55MM; Library Path: Y:\MIS_DATABASE\Library\ALTIUM_TOOL\SCHEMATICS_PARTS\MS_DISCRETE_Library.schlib; Manufacturer: TDK CORPORATION; Mfr_name: TDK CORPORATION; Mfr_part_number: C1005X5R1A475M; Mistral Part No: 120012060002-R; Package: 0402; Part_type: CAPACITORS\CERAMIC; Project: IRIS; RoHS: RoHS; Temperature: -55°C+85°C; Tolerance: 20%; Voltage: 10V; Wattage: NA; Weight: 0.65mg; Datasheet: Y:\MIS_DATABASE\DATASHEETS\CAPACITORS\TDK-C-SER_JUL17.PDF
FL8 FL9 FL26 FL27 = CAP_FILTER: PASSIVE FILTER EMI 0.47uF 0805; Chkd/date: RAGESH/121010; Crtd /date: MUDDU/010210; Custom_Duty: 24%; Customs_HS_Code: 85437099; Distributor_name: DIGIKEY; Distributor_part_number: 490-2537-1-ND; Height: 0.95MM; Manufacturer: MURATA; Mfr_name: MURATA; Mfr_part_number: NFM21PC474R1C3D; Mistral Part No: 130010010009; Package: 0805; Part_type: FILTER; Project: KOPIN_MODULS; Temperature: -55°C+125°C; Weight: NA; Datasheet: Y:\MIS_DATABASE\DATASHEETS\ICS\MISC\NFM21P.PDF
R210 R211 R218 R221 R231 R239 R240 R248 = RESISTOR: RES 49.9E 1/10W 1% 0402; Chkd/date: VASANTHA/201216; Crtd /date: MAZHAR/201005; Custom_Duty: 15%; Customs_HS_Code: 85332119; Distributor_name: DIGIKEY; Distributor_part_number: P49.9LCT-ND; Footprint Path: Y:\MIS_DATABASE\Library\ALTIUM_TOOL\PCB_FOOTPRINTS\Altium_Footprint_Lib.PcbLib; Height: 0.40MM; Library Path: Y:\MIS_DATABASE\Library\ALTIUM_TOOL\SCHEMATICS_PARTS\MS_DISCRETE_Library.schlib; Manufacturer: PANASONIC-ECG; Mfr_name: PANASONIC-ECG; Mfr_part_number: ERJ-2RKF49R9X; Mistral Part No: 110009030897-R; Package: 0402; Part_type: RESISTORS\FIXED; Project: RED EYE; RoHS: RoHS; Temperature: -55°C+155°C; Tolerance: 1%; Voltage: NA; Wattage: 1/10W; Weight: 0.8mg; Datasheet: Y:\MIS_DATABASE\DATASHEETS\RESISTORS\PAN-ERJSER_NOV17.PDF
R212 R214 R217 R219 R233 R238 R242 R246 = RESISTOR: RES 33E 1/10W 1% 0402; Chkd/date: VASANTHA/061216; Crtd /date: JEBRAN/171114; Custom_Duty: 15%; Customs_HS_Code: 85332119; Distributor_name: DIGIKEY; Distributor_part_number: P33.0LCT-ND; Footprint Path: Y:\MIS_DATABASE\Library\ALTIUM_TOOL\PCB_FOOTPRINTS\Altium_Footprint_Lib.PcbLib; Height: 0.40MM; Library Path: Y:\MIS_DATABASE\Library\ALTIUM_TOOL\SCHEMATICS_PARTS\MS_DISCRETE_Library.schlib; Manufacturer: PANASONIC-ECG; Mfr_name: PANASONIC-ECG; Mfr_part_number: ERJ-2RKF33R0X; Mistral Part No: 110014110006-R; Package: 0402; Part_type: RESISTORS\FIXED; Project: ZK BIOMETRIC; RoHS: RoHS; Temperature: -55°C+155°C; Tolerance: 1%; Voltage: NA; Wattage: 1/10W; Weight: 0.8mg; Datasheet: Y:\MIS_DATABASE\DATASHEETS\RESISTORS\PAN-ERJSER_NOV17.PDF
R224 R236 R917 R920 = RESISTOR: RES 4.7K 1/16W 5% 0402; Chkd/date: VASANTHA/130516; Crtd /date: VASANTHA/130516; Custom_Duty: 15%; Customs_HS_Code: 85332119; Distributor_name: DIGIKEY; Distributor_part_number: 311-4.7KJRCT-ND; Footprint Path: Y:\MIS_DATABASE\Library\ALTIUM_TOOL\PCB_FOOTPRINTS\Altium_Footprint_Lib.PcbLib; Height: 0.40MM; Library Path: Y:\MIS_DATABASE\Library\ALTIUM_TOOL\SCHEMATICS_PARTS\MS_DISCRETE_Library.schlib; Manufacturer: YAGEO AMERICA; Mfr_name: YAGEO AMERICA; Mfr_part_number: RC0402JR-074K7L; Mistral Part No: 110011060001-R; Package: 0402; Part_type: RESISTORS\FIXED; Project: TMDXCSK368; RoHS: RoHS; Temperature: -55°C+155°C; Tolerance: 5%; Voltage: NA; Wattage: 1/16W; Weight: 0.65mg; Datasheet: Y:\MIS_DATABASE\DATASHEETS\RESISTORS\RCXXXXL-SER_MAR18.PDF
R921 = RESISTOR: RES 4.7K 1/16W 5% 0402; Assembly_Instruction: DNI; Chkd/date: VASANTHA/130516; Crtd /date: VASANTHA/130516; Custom_Duty: 15%; Customs_HS_Code: 85332119; Distributor_name: DIGIKEY; Distributor_part_number: 311-4.7KJRCT-ND; Footprint Path: Y:\MIS_DATABASE\Library\ALTIUM_TOOL\PCB_FOOTPRINTS\Altium_Footprint_Lib.PcbLib; Height: 0.40MM; Library Path: Y:\MIS_DATABASE\Library\ALTIUM_TOOL\SCHEMATICS_PARTS\MS_DISCRETE_Library.schlib; Manufacturer: YAGEO AMERICA; Mfr_name: YAGEO AMERICA; Mfr_part_number: RC0402JR-074K7L; Mistral Part No: 110011060001-R; Package: 0402; Part_type: RESISTORS\FIXED; Project: TMDXCSK368; RoHS: RoHS; Temperature: -55°C+155°C; Tolerance: 5%; Voltage: NA; Wattage: 1/16W; Weight: 0.65mg; Datasheet: Y:\MIS_DATABASE\DATASHEETS\RESISTORS\RCXXXXL-SER_MAR18.PDF
U40 = CDCI6214RGET_VQFN24: IC PCIE GEN4 CLOCK GENERATOR WITH PROGRAMMABLE O/P AND EEPROM VQFN24; Chkd/date: MANIRAJA/051017; Crtd /date: MANIRAJA/051017; Custom_Duty: 15%; Customs_HS_Code: 85423100; Distributor_name: NA; Distributor_part_number: NA; Height: 1.00MM; Manufacturer: TEXAS INSTRUMENTS; Mfr_name: TEXAS INSTRUMENTS; Mistral Part No: 141017100002-R; Package: VQFN24; Part_type: ICS\DIGITAL\PERIPHERAL; Project: TI_SVB_MAXWELL_DUT; RoHS: RoHS; Temperature: -40°C+85°C; Tolerance: NA; Voltage: NA; Wattage: NA; Weight: NA; Datasheet: Y:\MIS_DATABASE\DATASHEETS\ICS\DIGITAL\PERIPHERAL\CDCI6214.PDF
Y4 = CRY: CRY 25.000MHz 18pF SMD; Chkd/date: VASANTHA/110316; Crtd /date: JEBRAN/090216; Custom_Duty: 24%; Customs_HS_Code: 85439000; Distributor_name: DIGIKEY; Distributor_part_number: CTX1175CT-ND; Footprint Path: Y:\MIS_DATABASE\Library\ALTIUM_TOOL\PCB_FOOTPRINTS\Altium_Footprint_Lib.PcbLib; Height: 1.35MM; Library Path: Y:\MIS_DATABASE\Library\ALTIUM_TOOL\SCHEMATICS_PARTS\MS_DISCRETE_Library.schlib; Manufacturer: CTS; Mfr_name: CTS; Mfr_part_number: 445I23D25M00000; Mistral Part No: 130016020016-R; Package: SMD; Part_type: CRYSTAL; Project: PDI_MINIPCB; RoHS: RoHS; Temperature: -40°C+85°C; Tolerance: NA; Voltage: NA; Wattage: NA; Weight: 50mg; Datasheet: Y:\MIS_DATABASE\DATASHEETS\MISC\CRY_OSC\445.PDF

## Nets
DGND: C162.1 C163.1 C164.2 C165.2 C166.1 C167.1 C168.2 C169.2 C186.1 C187.1 C190.2 C191.2 C196.2 C197.2 C259.2 C316.1 C317.1 C339.2 C342.2 C407.2 C410.2 C809.2 C810.2 C815.2 C816.2 C879.2 C886.2 C906.2 C937.2 C1043.2 C1049.2 C1063.2 C1075.1 C1082.2 C1089.2 C1105.1 C1162.2 C1163.2 C1164.2 C1165.2 C1168.2 C1170.2 C1171.2 C1192.2 C1212.2 C1213.2 FL8.2(GND1) FL9.2(GND1) FL26.2(GND1) FL27.2(GND1) J47.1 J54.1 J54.3 J54.5 J54.19 J54.20 J54.37 J54.38 J54.51 J54.52 J54.67 J54.68 J54.81 J54.82 J54.95 J54.96 J54.107 J54.108 J54.119 J54.120 J54.121 J54.122 J54.123 J54.124 J54.125 J54.126 J54.127 J54.128 J55.12 J55.16 J55.24 J55.SH1 J55.SH2 J55.SH3 J55.SH4 J56.1 J56.3 J56.5 J56.39 J56.40 J56.67 J56.68 J56.77 J56.79 J56.81 J56.105 J56.119 J56.120 J56.121 J56.122 J56.123 J56.124 J56.125 J56.126 J56.127 J56.128 J57.12 J57.16 J57.24 J57.SH1 J57.SH2 J57.SH3 J57.SH4 R210.2 R211.2 R218.2 R221.2 R231.2 R239.2 R240.2 R248.2 R469.1 R917.2 R920.2 R941.2 R1168.1 R1177.1 R1233.1 U40.25(GND) U80.2(1DIR) U80.3(2DIR) U80.8(GND1) U80.9(GND2) U80.14(~{2OE}) U80.15(~{1OE}) U88.1(GND) U242.11(GND) U242.21(PAD) U265.4(GND) ; also on sheet 11 12 13 14 15 16 17 18 20 21 22 23 24 25 26 27 28 29 33 34 35 36 37 38 39 40 41 42 43 44 45 46 47 48 49 50 51 52 53 54 55 56 57 58 59 60 61 62 63 64 65 66 67 68 69 70 71 72 73 76 77 78 79 81 82 83 84
V3V3_REF_CDCI1: C164.1 C165.1 C166.2 FL8.3(OUT) U40.3(VDDREF)
V3V3_VCO_CDCI1: C167.2 C168.1 C169.1 FL9.3(OUT) U40.24(VDDVCO)
VCC_12V0: C259.1 C407.1 C410.1 C879.1 C886.1 C906.1 C937.1 J47.2 J54.2 J54.4 J54.6 J55.1 J55.3 J57.1 J57.3 ; also on sheet 46 50 53 59 60 64 66 83
VCC_CSI_IO: C316.2 C342.1 C810.1 C816.1 C1105.2 C1163.1 C1165.1 C1192.1 J55.38 J55.40 J57.38 J57.40 R501.1 R510.1 R1134.1 R1233.2 R1240.2 R1241.2 TP225.1(TP) U80.1(VCCA) U88.2(VREF1) U242.2(VCCA)
VDD12_CDCI1: C187.2 C191.1 C197.1 FL27.3(OUT) U40.16(VDDO12)
VDD34_CDCI1: C186.2 C190.1 C196.1 FL26.3(OUT) U40.15(VDDO34)
BOARDID_EEPROM_WP: J56.25 ; also on sheet 35 43
CAN_STB: J54.102 ; also on sheet 38 81
CDCI1_EEPROMSEL: R917.1 R921.2 U40.23(EEPROMSEL)
CDCI1_OE1: R931.2 U40.20(STATUS/GPIO1)
CDCI1_OE1/OE4: R224.2 R931.1 U40.11(OE/GPIO4) ; also on sheet 38
CDCI1_OE2/OE3: R225.2 R230.1 R236.2 U40.19(SDA/GPIO2) ; also on sheet 38
CDCI1_OE3: R227.2 R230.2 U40.12(SCL/GPIO3)
CDCI1_REFSEL: R920.1 U40.4(REFSEL)
CDCI1_XIN: C163.2 U40.1(XIN) Y4.2
CDCI1_XOUT: C162.2 U40.2(XOUT) Y4.1
CDCI1_Y0: TP49.1(TP) U40.7(Y0)
CDCI1_Y1N: R219.1 U40.21(Y1N)
CDCI1_Y1P: R214.1 U40.22(Y1P)
CDCI1_Y2N: R246.1 U40.17(Y2N)
CDCI1_Y2P: R242.1 U40.18(Y2P)
CDCI1_Y3N: R233.1 U40.13(Y3N)
CDCI1_Y3P: R238.1 U40.14(Y3P)
CDCI1_Y4N: R212.1 U40.9(Y4N)
CDCI1_Y4P: R217.1 U40.10(Y4P)
CLKGEN_PCIE0_4L_REFCLK_N: R246.2 R248.1 ; also on sheet 59
CLKGEN_PCIE0_4L_REFCLK_P: R240.1 R242.2 ; also on sheet 59
CLKGEN_PCIE1_2L_REFCLK_N: R211.1 R212.2 ; also on sheet 60
CLKGEN_PCIE1_2L_REFCLK_P: R217.2 R218.1 ; also on sheet 60
CLKGEN_SERDES0_REFCLK_N: R219.2 R221.1 ; also on sheet 60
CLKGEN_SERDES0_REFCLK_P: R210.1 R214.2 ; also on sheet 60
CLKGEN_SERDES1_REFCLK_N: R231.1 R233.2 ; also on sheet 59
CLKGEN_SERDES1_REFCLK_P: R238.2 R239.1 ; also on sheet 59
CSI0_RX0_N: J57.11 ; also on sheet 11
CSI0_RX0_P: J57.9 ; also on sheet 11
CSI0_RX1_N: J57.15 ; also on sheet 11
CSI0_RX1_P: J57.13 ; also on sheet 11
CSI0_RX2_N: J57.19 ; also on sheet 11
CSI0_RX2_P: J57.17 ; also on sheet 11
CSI0_RX3_N: J57.23 ; also on sheet 11
CSI0_RX3_P: J57.21 ; also on sheet 11
CSI0_RXCLK_N: J57.7 ; also on sheet 11
CSI0_RXCLK_P: J57.5 ; also on sheet 11
CSI1_RX0_N: J57.31 ; also on sheet 11
CSI1_RX0_P: J57.29 ; also on sheet 11
CSI1_RX1_N: J57.35 ; also on sheet 11
CSI1_RX1_P: J57.33 ; also on sheet 11
CSI1_RX2_N: J57.39 ; also on sheet 11
CSI1_RX2_P: J57.37 ; also on sheet 11
CSI1_RX3_N: J57.28 ; also on sheet 11
CSI1_RX3_P: J57.26 ; also on sheet 11
CSI1_RXCLK_N: J57.27 ; also on sheet 11
CSI1_RXCLK_P: J57.25 ; also on sheet 11
CSI2_A_GPIO0_DV: J57.6 U80.4(1A1)
CSI2_A_GPIO1_DV: J57.8 U242.1(A1)
CSI2_A_GPIO2_DV: J57.18 U242.3(A2)
CSI2_A_GPIO3_DV: J57.20 U242.4(A3)
CSI2_A_GPIO4_DV: J57.22 U242.5(A4)
CSI2_A_REFCLK_DV: J57.10 U80.5(1A2)
CSI2_B_GPIO1_DV: J55.8 U242.6(A5)
CSI2_B_GPIO2_DV: J55.18 U242.7(A6)
CSI2_B_GPIO3_DV: J55.20 U242.8(A7)
CSI2_B_GPIO4_DV: J55.22 U242.9(A8)
CSI2_B_REFCLK_DV: J55.10 U80.6(2A1)
CSI2_EXP_A_GPIO0: U80.13(1B1) ; also on sheet 38
CSI2_EXP_A_GPIO1: U242.20(B1) ; also on sheet 38
CSI2_EXP_A_GPIO2: U242.18(B2) ; also on sheet 20
CSI2_EXP_A_GPIO3: U242.17(B3) ; also on sheet 38
CSI2_EXP_A_GPIO4: U242.16(B4) ; also on sheet 20
CSI2_EXP_B_GPIO1: U242.15(B5) ; also on sheet 38
CSI2_EXP_B_GPIO2: U242.14(B6) ; also on sheet 38
CSI2_EXP_B_GPIO3: U242.13(B7) ; also on sheet 38
CSI2_EXP_B_GPIO4: U242.12(B8) ; also on sheet 38
CSI2_EXP_RSTz: R469.2 U80.10(2B2) ; also on sheet 38
CSI2_I2C_SCL_DV: J55.2 J57.2 R510.2 U88.3(SCL1)
CSI2_I2C_SDA_DV: J55.4 J57.4 R501.2 U88.4(SDA1)
CSI2_REFCLK: U80.11(2B1) U80.12(1B2) ; also on sheet 34
CSI2_RSTz_DV: J55.14 J57.14 R471.1
CSI2_RX0_N: J55.11 ; also on sheet 11
CSI2_RX0_P: J55.9 ; also on sheet 11
CSI2_RX1_N: J55.15 ; also on sheet 11
CSI2_RX1_P: J55.13 ; also on sheet 11
CSI2_RX2_N: J55.19 ; also on sheet 11
CSI2_RX2_P: J55.17 ; also on sheet 11
CSI2_RX3_N: J55.23 ; also on sheet 11
CSI2_RX3_P: J55.21 ; also on sheet 11
CSI2_RXCLK_N: J55.7 ; also on sheet 11
CSI2_RXCLK_P: J55.5 ; also on sheet 11
CSI_VIO_SEL: U265.1(EN1) ; also on sheet 35
EXP_3V3: C809.1 C815.1 C1162.1 C1164.1 C1168.1 C1170.1 C1171.1 J55.30 J55.32 J55.34 J55.36 J56.2 J56.4 J56.6 J57.30 J57.32 J57.34 J57.36 ; also on sheet 59 60 65
EXP_EEPROM_A0: J56.19 R1177.2
EXP_EEPROM_A1: J56.21 R1171.2
EXP_EEPROM_A2: J56.23 R1168.2
EXP_MUX2: J56.34 ; also on sheet 38
EXP_MUX3: J56.36 ; also on sheet 38
EXP_REFCLK: J56.22 ; also on sheet 34
EXP_RSTz: J54.118 ; also on sheet 37
GESI_GPIO_RGMII1_RST#: J56.29 ; also on sheet 38
GESI_MCAN4_RX: J54.55 ; also on sheet 19
GESI_MCAN4_TX: J54.53 ; also on sheet 19
GESI_MDIO0_MDC: J54.97 ; also on sheet 19
GESI_MDIO0_MDIO: J54.99 ; also on sheet 19
GESI_RGMII1_INT#: J56.15 ; also on sheet 19
GESI_RGMII1_RD0: J54.69 ; also on sheet 19
GESI_RGMII1_RD1: J54.77 ; also on sheet 19
GESI_RGMII1_RD2: J54.75 ; also on sheet 19
GESI_RGMII1_RD3: J54.79 ; also on sheet 19
GESI_RGMII1_RX_CTL: J54.71 ; also on sheet 19
GESI_RGMII1_RXC: J54.73 ; also on sheet 19
GESI_RGMII1_TD0: J54.72 ; also on sheet 19
GESI_RGMII1_TD1: J54.70 ; also on sheet 19
GESI_RGMII1_TD2: J54.78 ; also on sheet 19
GESI_RGMII1_TD3: J54.76 ; also on sheet 19
GESI_RGMII1_TX_CTL: J54.74 ; also on sheet 19
GESI_RGMII1_TXC: J54.80 ; also on sheet 19
GESI_RMII8_CLKOUT: TP117.1(TP) ; also on sheet 19
GESI_RMII8_CRS_DV: J56.64 ; also on sheet 19
GESI_RMII8_PHY_INTn: J56.56 ; also on sheet 19
GESI_RMII8_REF_CLK: J54.54 ; also on sheet 19
GESI_RMII8_RX_ER: J56.58 ; also on sheet 19
GESI_RMII8_RXD0: J56.44 ; also on sheet 19
GESI_RMII8_RXD1: J56.48 ; also on sheet 19
GESI_RMII8_TX_EN: J56.62 ; also on sheet 19
GESI_RMII8_TXD0: J56.60 ; also on sheet 19
GESI_RMII8_TXD1: J56.46 ; also on sheet 19
GESI_SPI5_CLK: J54.105 ; also on sheet 19
GESI_SPI5_CS0: J54.59 ; also on sheet 19
GESI_SPI5_CS1: J54.57 ; also on sheet 19
GESI_SPI5_D0: J54.101 ; also on sheet 19
GESI_SPI5_D1: J54.103 ; also on sheet 19
GESI_UART8_RXD: J56.7 ; also on sheet 19
GESI_UART8_TXD: J56.9 ; also on sheet 19
GESI_UART9_RXD: J56.88 ; also on sheet 19
GESI_UART9_TXD: J56.90 ; also on sheet 19
GPIO_LIN_EN: J54.110 ; also on sheet 38 46
GPIO_PRG1_RGMII_RST: J54.66 R941.1
I2C0_SCL: R227.1 ; also on sheet 20 33 34 38 58 59
I2C0_SDA: R225.1 ; also on sheet 20 33 34 38 58 59
I2C5_SCL: U88.6(SCL2) ; also on sheet 20 38
I2C5_SDA: U88.5(SDA2) ; also on sheet 20 38
MCU_ADC1_AIN0: J56.83 ; also on sheet 21 58
MCU_ADC1_AIN1: J56.85 ; also on sheet 21 58
MCU_ADC1_AIN2: J56.87 ; also on sheet 21
MCU_ADC1_AIN3: J56.89 ; also on sheet 21
MCU_ADC1_AIN4: J56.91 ; also on sheet 21
MCU_ADC1_AIN5: J56.93 ; also on sheet 21
MCU_ADC1_AIN6: J56.95 ; also on sheet 21
MCU_ADC1_AIN7: J56.97 ; also on sheet 21
MCU_ADC_EXT_TRIGGER1: J56.103 ; also on sheet 18
PERIPH_RSTz: J56.28 ; also on sheet 37 38
R_CSI2_RSTz_DV: R471.2 U80.7(2A2)
RESETSTATZ: J56.30 ; also on sheet 18 37 62
RGMII_REFCLK: J54.106 ; also on sheet 34
SOC_PORZ_OUT: J54.64 U40.8(RESETN/SYNC) ; also on sheet 18 37 43 51 56 59 60 62 69
TXS0108_OE: R1134.2 U242.10(OE)
USB1_DN4_D_N: J56.115 ; also on sheet 51
USB1_DN4_D_P: J56.117 ; also on sheet 51
USB1_DN4_PE: J56.113 ; also on sheet 51
VLDO_CSI_1V8: R1241.1 U265.5(OUT2)
VLDO_CSI_3V3: R1240.1 U265.6(OUT1)
VREF2_CSI: C339.1 R522.2 U88.7(VREF2) U88.8(EN)
VSYS_5V0: C1082.1 C1089.1 C1212.1 C1213.1 J56.78 J56.80 J56.82 U265.2(IN) U265.3(EN2) ; also on sheet 20 50 52 59 65 68 72 81 82 83 84
VSYS_IO_1V8: C1043.1 C1049.1 FL26.1(IN) FL27.1(IN) J56.114 J56.116 J56.118 ; also on sheet 33 34 37 38 41 42 61 65 75
VSYS_IO_3V3: C317.2 C1063.1 C1075.2 FL8.1(IN) FL9.1(IN) J56.100 J56.102 J56.104 R224.1 R236.1 R522.1 R921.1 U80.16(VCCB) U242.19(VCCB) ; also on sheet 18 20 22 24 29 33 35 36 37 38 40 41 42 43 45 46 48 50 51 53 56 57 58 59 60 61 65 66 68 75 81 82
WKUP_I2C0_SCL: J54.65 ; also on sheet 43
WKUP_I2C0_SDA: J54.63 ; also on sheet 43
N26472696: R1171.1 TP196.1(TP)

Not connected (* = marked no-connect by the designer): J54 7* 8* 9* 10* 11* 12* 13* 14* 15* 16* 17* 18* 21* 22* 23* 24* 25* 26* 27* 28* 29* 30* 31* 32* 33* 34* 35* 36* 39* 40* 41* 42* 43* 44* 45* 46* 47* 48* 49* 50* 56* 58* 60* 61* 62* 83* 84* 85* 86* 87* 88* 89* 90* 91* 92* 93* 94* 98* 100* 104* 109* 111* 112* 113* 114* 115* 116* 117*; J55 6* 25* 26* 27* 28* 29* 31* 33* 35* 37* 39*; J56 8* 10* 11* 12* 13* 14* 16* 17* 18* 20* 24* 26* 27* 31* 32* 33* 35* 37* 38* 41* 42* 43* 45* 47* 49* 50* 51* 52* 53* 54* 55* 57* 59* 61* 63 65* 66* 69* 70* 71* 72* 73* 74* 75* 76* 84* 86* 92* 94* 96* 98* 99* 101* 106* 107 108* 109 110* 111* 112*; U40 5(REFP)* 6(REFN)*

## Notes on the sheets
sheet 30
- GESI_EXP_CONN
- Silkscreen  "GESI BRD CONN"
- Place test point near Expansion connector
- SPI3_MOSI
- SPI3_MISO
- Silkscreen  "GESI BRD CONN"
- [Optional CLK]
- EEPROM ADDRESS: 0x52
- 90E
sheet 31
- CSI2 EXPANSION CONNECTORS
- Level Translation for LVCMOS
- Auxiliary 12V Power Output for CSI2
- Silkscreen "EXP_PWR"
- [SCL]
- [SDA]
- [GPIO/PWM_A]
- [GPIO/PWM_B]
- [25M REFCLK]
- CSI2
- [RESETz]
- Port 0
- [MOSI/GPIO]
- [SCLK/GPO]
- [CS/GPIO]
- [3V3]
- CSI2
- [VIO]
- Port 1
- Silkscreen "CSI CONN"
- DIR LOW: 1B --> 1A
      LOW: 2B --> 2A
- [SCL]
- [SDA]
- [GPIO/PWM_B]
- [25M REFCLK]
- [RESETz]
- CSI2
- [MOSI/GPIO]
- Port 2
- [SCLK/GPO]
- [CS/GPIO]
- [3V3]
- [VIO]
- CSI2_EXP_A_GPIO2, 4 are connected to SOC GPIO
  and others are from IO expander
- Silkscreen "CSI CONN"
- LVCMOS IO Voltage Selection
- See DIP Switch for Selection Control
- Note: Resistor is to 'bleed' off voltage.
sheet 32
- SERDES CLOCK GENERATOR #1
- 100E
- 100MHz HCSL Clock  for
  SOC SERDES1(PCIe1)
- 100E
- PCIe REF clock for PCIe
  0Con (x4 lane) (100MHz
  HCSL)
- 100E
- PCIe REF clock for
  SOC_SERDES01(PCIe0) (100MHz HCSL)
- REFSEL- 0 selects crystal reference
- 100E
- PCIe REF clock for PCIe1  Con
  (x2 lane) (100MHz HCSL)
- From GPIO EXP
- R211,R218,R231 & R239 need to be mounted when PCIe0 ref clock is from Clock generator
- EEPROMSEL - LOW  - Page-0 (default)
  EEPROMSEL - HIGH - Page-1
